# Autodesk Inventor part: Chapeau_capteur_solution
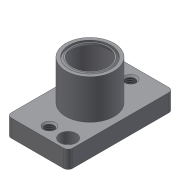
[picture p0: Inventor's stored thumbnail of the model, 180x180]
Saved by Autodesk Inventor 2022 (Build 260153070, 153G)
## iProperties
Created: 2018-06
Part Number: Chapeau_capteur_solution
Material: Aluminium 6061
Document SubType Name: Modeling
Designer: Fabian Perrée
Density: 2.7 g/cm^3
Appearance: Générique
Mass: 26.5554 g
Surface Area: 66.9581 cm^2
Volume: 9.83534 cm^3
Author: Fabian Perrée
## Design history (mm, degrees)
sketch "Esquisse1"
  geometry: L1 (-14, 24)-(14, 24); L2 (14, 24)-(14, -24); L3 (14, -24)-(-14, -24); L4 (-14, -24)-(-14, 24); L5 (-14, 24)-(14, -24); L6 (14, 24)-(-14, -24); 1 further point
  constraints: 12 end point, 2 midpoint, 2 parallel, 1 horizontal, 1 perpendicular
  dimensions: "d0" = 28 distance of L2.end L3.end; "d1" = 48 distance of L1.end L2.end
extrude "Extrusion1" new body sketch "Esquisse1" distance "d2" = 8; taper "d3" = 0 deg
sketch "Esquisse2"
  geometry: L1 (0, 0)-(8, 0); L2 (8, -24)-(8, 24) reference; L3 (26, -11)-(26, -9.5); L4 (26, -9.5)-(25, -9.5); L5 (25, -9.5)-(26, -8.5); L6 (26, -8)-(24.268, -9); L7 (24.268, -9)-(8, -9); L8 (8, -9)-(8, -11); L9 (26, -11)-(8, -11); L10 (26, -8.5)-(26, -8); L11 (8, -9)-(2.5, -9); L12 (2.5, -9)-(2.5, -11.5); L13 (2.5, -11.5)-(0, -11.5); L14 (0, 24)-(0, -24) reference; L15 (0, -11.5)-(0, 0); L16 (8, -9)-(8, 0); L17 (8, 0)-(26, 0)
  constraints: 30 end point, 5 point on line, 4 horizontal, 4 perpendicular, 2 collinear, 2 vertical, 1 midpoint
  dimensions: "d4" = 18 distance from line of L2 L17.end; "d5" = 1.5 distance of L3.start L3.end; "d6" = 1 distance of L3.end L4.end; "d7" = 45 deg angle of L4 L5; "d8" = 150 deg angle of L7 L6; "d9" = 22 diameter of L9 L1; "d10" = 16 diameter of L6.start L1; "d11" = 18 diameter of L7 L1; "d12" = 23 diameter of L13 L1; "d13" = 18 diameter of L11 L1; "d14" = 2.5 distance of L12.end L13.end
revolve "Révolution1" stored, may be unused: angle "d15" = 90 deg
revolve "Révolution2" stored, may be unused: angle "d16" = 90 deg
sketch "Esquisse3"
  geometry: L1 (14, -24)-(14, 24) reference; L2 (-14, -24)-(14, -24) reference; L3 (-14, 24)-(-14, -24) reference; L4 (14, 24)-(-14, 24) reference; 3 further points
  dimensions: "d17" = 5 distance from line of L1 point (9, -19); "d18" = 5 distance from line of L2 point (9, -19); "d19" = 5 distance from line of L3 point (-9, 19); "d20" = 5 distance from line of L4 point (-9, 19)
hole "Perçage1" sketch "Esquisse3" at (-9, 19), (9, -19) diameter "d21" = 4.5; stored, may be unused: countersink angle "d25" = 90 deg, drill point angle "d27" = 118 deg; dims "d22" = 6, "d23" = 7.5, "d24" = 5, "d26" = 8
sketch "Esquisse4"
  geometry: L1 (-14, 24)-(-14, -24) reference; L2 (-14, -24)-(14, -24) reference; L3 (14, 24)-(-14, 24) reference; 4 further points
  constraints: 2 vertical alignment, 1 midpoint
  dimensions: "d29" = 5.5 distance from line of L2 point (0, -18.5) (= d31); "d31" = 5.5 distance from line of L3 point (0, 18.5)
hole "Perçage2" sketch "Esquisse4" at (0, -18.5), (0, 18.5) diameter "d32" = 4.134; stored, may be unused: countersink angle "d36" = 90 deg, drill point angle "d38" = 118 deg; dims "d33" = 10, "d34" = 5.5, "d35" = 5, "d37" = 14.2
fillet "Congé1" dims "d51" = 2
feature "Scission1"
node "Solide1"
